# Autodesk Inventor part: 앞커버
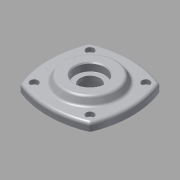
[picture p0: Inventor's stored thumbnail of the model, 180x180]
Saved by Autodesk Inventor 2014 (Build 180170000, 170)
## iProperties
Created: 2013-02
Part Number: 앞커버
Document SubType Name: Modeling
Designer: 한국산업디자인학원[gmhk.co.kr]
Density: 2.71 g/cm^3
Material: 알루미늄 6061
Appearance: 알루미늄 - 평지
Mass: 206.617 g
Surface Area: 198.108 cm^2
Volume: 76.2425 cm^3
Author: 한국산업디자인학원[gmhk.co.kr]
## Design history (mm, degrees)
sketch "스케치1"
  geometry: C1 r 30 at (0, 0) reference; A1 r 91.05 centre (0, -48.55) between (34.185, 35.839) and (-34.185, 35.839) reference; A2 r 91.05 centre (48.55, 0) between (-35.839, 34.185) and (-35.839, -34.185) reference; A3 r 3 centre (-33.058, 33.058) between (-34.185, 35.839) and (-35.839, 34.185) reference; A4 r 3 centre (33.058, 33.058) between (35.839, 34.185) and (34.185, 35.839) reference; A5 r 91.05 centre (-48.55, 0) between (35.839, -34.185) and (35.839, 34.185) reference; A6 r 3 centre (33.058, -33.058) between (34.185, -35.839) and (35.839, -34.185) reference; A7 r 91.05 centre (0, 48.55) between (-34.185, -35.839) and (34.185, -35.839) reference; A8 r 3 centre (-33.058, -33.058) between (-35.839, -34.185) and (-34.185, -35.839) reference; 1 further point
  node "참조1"
  node "참조2"
  node "참조3"
  node "참조4"
  node "참조5"
  node "참조6"
  node "참조7"
  node "참조8"
  node "참조9"
extrude "돌출1" new body sketch "스케치1" distance "d0" = 8; taper "d1" = 0 deg
sketch "스케치2"
  geometry: C1 r 30 at (0, 0); 1 further point
  constraints: 1 centre point, 1 coincident
  dimensions: "d2" = 60 diameter of C1
extrude "돌출2" join sketch "스케치2" distance "d3" = 7; taper "d4" = -30 deg
hole "구멍1" diameter "d7" = 20; stored, may be unused: countersink angle "d11" = 90 deg, drill point angle "d13" = 118 deg; dims "d5" = 10, "d6" = 10, "d8" = 6, "d9" = 30, "d10" = 8, "d12" = 20
sketch "스케치3"
  geometry: C1 r 1.621 at (28.284, 28.284) reference; C2 r 1.621 at (-28.284, 28.284) reference; C3 r 1.621 at (-28.284, -28.284) reference; C4 r 1.621 at (28.284, -28.284) reference; 1 further point
hole "구멍2" sketch "스케치3" at (28.284, 28.284), (28.284, -28.284), (-28.284, -28.284), (-28.284, 28.284) diameter "d14" = 4.5; stored, may be unused: countersink angle "d18" = 90 deg, drill point angle "d20" = 118 deg; dims "d15" = 6, "d16" = 8, "d17" = 4.4, "d19" = 20
extrude "돌출3" join sketch "스케치1" distance "d21" = 12; taper "d22" = 0 deg
hole "구멍3" diameter "d25" = 30; stored, may be unused: countersink angle "d29" = 90 deg, drill point angle "d31" = 0 deg; dims "d23" = 10, "d24" = 10, "d26" = 6, "d27" = 40, "d28" = 12, "d30" = 15
fillet "모깎기1" dims "d32" = 3, "d33" = 0.3
chamfer "모따기1" distance "d34" = 1; stored, may be unused: second distance "d35" = 2, angle "d36" = 45 deg
node "솔리드1"
node "참조10"
node "참조11"
node "참조12"
node "참조13"
